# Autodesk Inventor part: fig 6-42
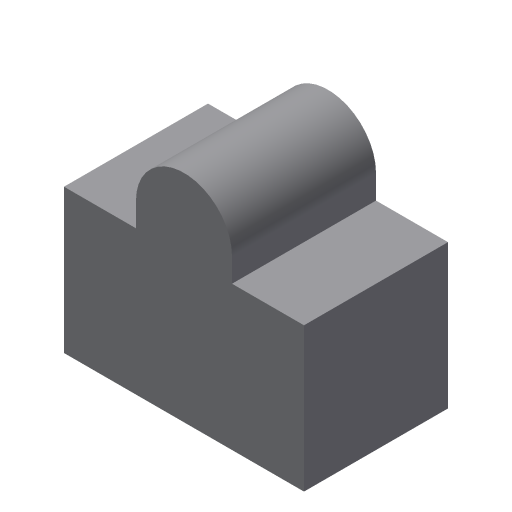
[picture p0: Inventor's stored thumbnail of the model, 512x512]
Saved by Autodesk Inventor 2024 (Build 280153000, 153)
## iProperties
Created: 2005-12
Part Number: fig 6-42
Document SubType Name: Modeling
Designer: CADCIM
Density: 1 g/cm^3
Material: Generic
Appearance: Default
Author: CADCIM
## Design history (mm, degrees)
sketch "Sketch1"
  geometry: L1 (10, 15)-(25, 15); L2 (25, 15)-(25, -15); L3 (25, -15)-(-25, -15); L4 (-25, -15)-(-25, 15); L5 (-25, 15)-(-10, 15); L6 (10, 15)-(10, 30); L7 (10, 30)-(-10, 30); L8 (-10, 30)-(-10, 15)
  constraints: 16 end point, 3 parallel, 3 perpendicular, 2 equal length, 1 collinear, 1 horizontal
  dimensions: "d0" = 50 distance of L2.end L3.end; "d2" = 30 distance of L1.end L2.end; "d3" = 15 distance of L1.start L1.end; "d11" = 15 distance of L7.end L5.end
extrude "Extrusion1" new body sketch "Sketch1" stored distance "d7" = 30; taper "d8" = 0 deg
fillet "Fillet5"
body "Solid1"
